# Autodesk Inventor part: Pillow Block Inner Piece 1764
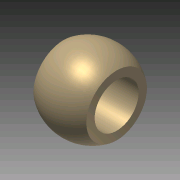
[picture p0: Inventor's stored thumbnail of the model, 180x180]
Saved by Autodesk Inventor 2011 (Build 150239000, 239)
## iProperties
Created: 2009-01
Part Number: Pillow Block Inner Piece 1764
Document SubType Name: Modeling
Designer: lwoods
Density: 1.4 g/cm^3
Material: PVC-Piping
Mass: 9.20302 g
Surface Area: 29.8864 cm^2
Volume: 6.57359 cm^3
Author: lwoods
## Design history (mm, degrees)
sketch "Sketch1"
  geometry: L1 (-16.593, 9.074)-(2.534, 9.074); L2 (-16.593, 9.074)-(-16.593, 12.071); L3 (2.534, 9.074)-(2.534, 12.071); L4 (-16.593, 12.071)-(2.534, 12.071); L5 (-7.029, 12.071)-(-7.029, 15.246); L6 (-28, 1.137)-(15.926, 1.137); A1 r 15.99 centre (-7.029, -0.743) between (2.534, 12.071) and (-16.593, 12.071)
  constraints: 12 end point, 3 point on circle, 2 perpendicular, 1 centre point, 1 horizontal, 1 midpoint, 1 parallel
  dimensions: "d0" = 0 vertical distance of L3.end L2.end; "d1" = 3.175 distance of L5.start L5.end; "d2" = 19.1262 distance of L1.start L1.end; "d3" = 2.9972 distance of L1.start L2.end; "d4" = 7.9375 distance from line of L6 L1.end
revolve "Revolution1" sketch "Sketch1" stored, may be unused: angle "d5" = 90 deg
body "Solid1"
